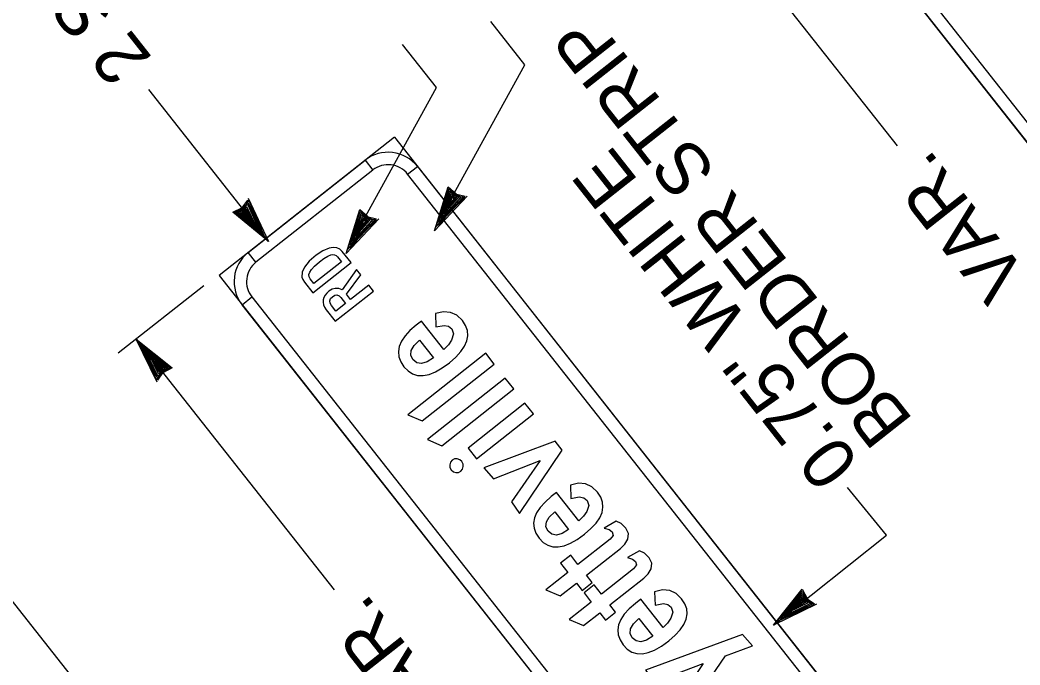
# Model space of a CAD drawing. Extents: x 672126 to 673696, y 1673540 to 1674900.
# Drawn here: x 672217.5 to 672298.2, y 1674630.5 to 1674682.5 of the extents above; entities that cross this region are included whole.
import ezdxf

# ---------------------------------------------------------------- set-up
doc = ezdxf.new("R2010")
doc.units = 0
for name, color, linetype in [('61', 7, 'Continuous'), ('C-ANNO-SYMB', 7, 'Continuous'), ('Level 1', 7, 'Continuous')]:
    doc.layers.add(name, color=color, linetype=linetype)

msp = doc.modelspace()

# ---------------------------------------------------------------- linework, layer by layer
at = {"layer": '61'}
msp.add_lwpolyline([(672259.689, 1674581.406), (672186.159, 1674674.677), (672163.206, 1674656.582), (672236.736, 1674563.312)], close=True, dxfattribs=at)
at = {"layer": 'C-ANNO-SYMB'}
for p, q in [((672275.262, 1674702.456), (672319.838, 1674645.914)), ((672247.706, 1674673.092), (672233.571, 1674661.948)), ((672247.706, 1674673.092), (672288.567, 1674621.261)), ((672245.35, 1674671.234), (672245.969, 1674670.449)), ((672248.778, 1674670.117), (672249.564, 1674670.736)), ((672236.546, 1674663.02), (672235.927, 1674663.805)), ((672233.571, 1674661.948), (672274.431, 1674610.117)), ((672235.428, 1674659.592), (672236.213, 1674660.211))]:
    msp.add_line(p, q, dxfattribs=at)
for points in [[(672277.905, 1674700.719), (672318.766, 1674648.889), (672317.98, 1674648.27), (672277.12, 1674700.1), (672277.905, 1674700.719), (672277.905, 1674700.719)], [(672245.969, 1674670.449), (672236.546, 1674663.02), (672235.927, 1674663.805), (672245.35, 1674671.234), (672245.969, 1674670.449), (672245.969, 1674670.449)], [(672285.924, 1674622.998), (672248.778, 1674670.117), (672249.564, 1674670.736), (672286.71, 1674623.617), (672285.924, 1674622.998), (672285.924, 1674622.998)], [(672236.213, 1674660.211), (672273.359, 1674613.092), (672272.574, 1674612.473), (672235.428, 1674659.592), (672236.213, 1674660.211), (672236.213, 1674660.211)], [(672255.756, 1674654.804), (672255.071, 1674655.674), (672248.788, 1674650.721), (672249.95, 1674650.227)], [(672257.341, 1674652.794), (672256.656, 1674653.664), (672250.373, 1674648.711), (672251.535, 1674648.217)], [(672258.926, 1674650.784), (672258.24, 1674651.653), (672253.65, 1674648.034), (672254.335, 1674647.165)], [(672257.802, 1674642.767), (672261.237, 1674647.852), (672260.664, 1674648.579), (672254.912, 1674646.433), (672255.696, 1674645.551), (672259.462, 1674647.025), (672257.166, 1674643.686)], [(672253.076, 1674646.172), (672253.212, 1674646.33), (672253.267, 1674646.532), (672253.246, 1674646.746), (672253.141, 1674646.939), (672252.975, 1674647.092), (672252.775, 1674647.168), (672252.569, 1674647.161), (672252.375, 1674647.061), (672252.233, 1674646.896), (672252.169, 1674646.69), (672252.19, 1674646.473), (672252.295, 1674646.273), (672252.465, 1674646.124), (672252.673, 1674646.058), (672252.888, 1674646.072)], [(672264.626, 1674641.585), (672265.042, 1674641.455), (672265.278, 1674641.283), (672265.345, 1674640.996), (672265.1, 1674640.689), (672262.516, 1674638.652), (672261.937, 1674639.386), (672261.117, 1674638.74), (672261.696, 1674638.006), (672259.918, 1674636.604), (672261.08, 1674636.109), (672262.382, 1674637.136), (672262.842, 1674636.553), (672263.662, 1674637.199), (672263.202, 1674637.782), (672265.933, 1674639.935), (672266.301, 1674640.292), (672266.526, 1674640.675), (672266.582, 1674641.142), (672266.385, 1674641.57), (672266.004, 1674641.941), (672265.584, 1674642.13)], [(672266.508, 1674639.198), (672266.924, 1674639.067), (672267.16, 1674638.895), (672267.227, 1674638.609), (672266.982, 1674638.302), (672264.398, 1674636.265), (672263.819, 1674636.999), (672263, 1674636.353), (672263.578, 1674635.619), (672261.8, 1674634.217), (672262.962, 1674633.722), (672264.264, 1674634.748), (672264.724, 1674634.165), (672265.544, 1674634.812), (672265.084, 1674635.394), (672267.815, 1674637.547), (672268.183, 1674637.904), (672268.408, 1674638.287), (672268.464, 1674638.754), (672268.267, 1674639.183), (672267.886, 1674639.553), (672267.466, 1674639.743)], [(672276.595, 1674632.098), (672275.794, 1674632.989), (672267.961, 1674630.13), (672268.701, 1674629.191), (672272.617, 1674630.656), (672270.294, 1674627.171), (672270.999, 1674626.277), (672274.405, 1674631.287)]]:
    msp.add_lwpolyline(points, close=True, dxfattribs=at)
for points in [[(672244.214, 1674662.985), (672243.506, 1674663.882), (672243.306, 1674664.07), (672243.061, 1674664.177), (672242.775, 1674664.203), (672242.443, 1674664.148), (672241.926, 1674663.936), (672241.4, 1674663.587), (672240.842, 1674663.092), (672240.463, 1674662.629), (672240.265, 1674662.201), (672240.246, 1674661.807), (672240.322, 1674661.618), (672240.47, 1674661.398), (672241.133, 1674660.556), (672244.214, 1674662.985)], [(672243.436, 1674663.057), (672241.209, 1674661.301), (672240.924, 1674661.662), (672240.834, 1674661.832), (672240.819, 1674662.018), (672240.881, 1674662.218), (672241.017, 1674662.433), (672241.269, 1674662.697), (672241.673, 1674663.038), (672242.021, 1674663.313), (672242.337, 1674663.508), (672242.578, 1674663.611), (672242.743, 1674663.636), (672242.89, 1674663.615), (672243.022, 1674663.549), (672243.135, 1674663.439), (672243.436, 1674663.057)], [(672246.022, 1674660.692), (672245.641, 1674661.175), (672244.174, 1674660.018), (672243.85, 1674660.43), (672244.999, 1674661.989), (672244.65, 1674662.431), (672243.485, 1674660.786), (672243.226, 1674660.892), (672242.942, 1674660.904), (672242.68, 1674660.831), (672242.432, 1674660.682), (672242.258, 1674660.523), (672242.123, 1674660.353), (672242.029, 1674660.173), (672241.975, 1674659.984), (672241.964, 1674659.781), (672242.001, 1674659.58), (672242.084, 1674659.381), (672242.214, 1674659.185), (672242.941, 1674658.263), (672246.022, 1674660.692)], [(672243.768, 1674659.699), (672242.983, 1674659.08), (672242.627, 1674659.532), (672242.529, 1674659.711), (672242.509, 1674659.901), (672242.57, 1674660.081), (672242.711, 1674660.236), (672242.902, 1674660.347), (672243.079, 1674660.372), (672243.246, 1674660.312), (672243.4, 1674660.166), (672243.768, 1674659.699)], [(672251.693, 1674655.984), (672249.889, 1674658.272), (672249.464, 1674657.937), (672248.964, 1674657.5), (672248.567, 1674657.067), (672248.282, 1674656.641), (672248.102, 1674656.221), (672248.035, 1674655.804), (672248.074, 1674655.394), (672248.225, 1674654.989), (672248.48, 1674654.592), (672248.813, 1674654.252), (672249.18, 1674654.018), (672249.585, 1674653.894), (672250.023, 1674653.881), (672250.503, 1674653.975), (672251.015, 1674654.18), (672251.563, 1674654.493), (672252.15, 1674654.915), (672252.668, 1674655.364), (672253.076, 1674655.805), (672253.374, 1674656.239), (672253.558, 1674656.665), (672253.636, 1674657.084), (672253.598, 1674657.499), (672253.451, 1674657.906), (672253.192, 1674658.305), (672252.747, 1674658.734), (672252.236, 1674658.972), (672251.66, 1674659.02), (672251.014, 1674658.875), (672251.051, 1674657.795), (672251.725, 1674657.923), (672252.081, 1674657.851), (672252.347, 1674657.639), (672252.484, 1674657.236), (672252.327, 1674656.736), (672252.061, 1674656.351), (672251.693, 1674655.984)], [(672250.866, 1674655.293), (672250.349, 1674654.971), (672249.899, 1674654.842), (672249.518, 1674654.906), (672249.205, 1674655.162), (672249.037, 1674655.516), (672249.068, 1674655.896), (672249.304, 1674656.296), (672249.74, 1674656.721), (672250.866, 1674655.293)], [(672262.589, 1674642.163), (672260.785, 1674644.45), (672260.36, 1674644.115), (672259.86, 1674643.679), (672259.463, 1674643.246), (672259.178, 1674642.82), (672258.998, 1674642.4), (672258.932, 1674641.983), (672258.971, 1674641.572), (672259.122, 1674641.168), (672259.376, 1674640.771), (672259.709, 1674640.431), (672260.076, 1674640.197), (672260.481, 1674640.072), (672260.919, 1674640.059), (672261.399, 1674640.154), (672261.911, 1674640.358), (672262.46, 1674640.672), (672263.046, 1674641.094), (672263.564, 1674641.542), (672263.972, 1674641.983), (672264.27, 1674642.418), (672264.454, 1674642.844), (672264.532, 1674643.263), (672264.495, 1674643.677), (672264.348, 1674644.085), (672264.088, 1674644.483), (672263.643, 1674644.912), (672263.132, 1674645.15), (672262.556, 1674645.198), (672261.91, 1674645.053), (672261.947, 1674643.973), (672262.621, 1674644.102), (672262.977, 1674644.029), (672263.243, 1674643.817), (672263.38, 1674643.414), (672263.224, 1674642.914), (672262.957, 1674642.53), (672262.589, 1674642.163)], [(672261.762, 1674641.471), (672261.245, 1674641.149), (672260.795, 1674641.021), (672260.414, 1674641.085), (672260.102, 1674641.341), (672259.934, 1674641.694), (672259.965, 1674642.075), (672260.2, 1674642.474), (672260.636, 1674642.9), (672261.762, 1674641.471)], [(672269.374, 1674633.555), (672267.571, 1674635.843), (672267.146, 1674635.508), (672266.646, 1674635.072), (672266.248, 1674634.639), (672265.963, 1674634.213), (672265.784, 1674633.793), (672265.717, 1674633.376), (672265.756, 1674632.965), (672265.907, 1674632.561), (672266.161, 1674632.164), (672266.494, 1674631.823), (672266.861, 1674631.589), (672267.267, 1674631.465), (672267.705, 1674631.452), (672268.185, 1674631.547), (672268.696, 1674631.751), (672269.245, 1674632.065), (672269.831, 1674632.487), (672270.349, 1674632.935), (672270.758, 1674633.376), (672271.056, 1674633.811), (672271.24, 1674634.237), (672271.317, 1674634.656), (672271.28, 1674635.07), (672271.133, 1674635.478), (672270.873, 1674635.876), (672270.428, 1674636.305), (672269.918, 1674636.543), (672269.341, 1674636.591), (672268.696, 1674636.446), (672268.733, 1674635.366), (672269.406, 1674635.495), (672269.763, 1674635.422), (672270.028, 1674635.21), (672270.166, 1674634.807), (672270.009, 1674634.307), (672269.742, 1674633.923), (672269.374, 1674633.555)], [(672268.548, 1674632.864), (672268.03, 1674632.542), (672267.581, 1674632.414), (672267.2, 1674632.478), (672266.887, 1674632.734), (672266.719, 1674633.087), (672266.75, 1674633.468), (672266.986, 1674633.867), (672267.421, 1674634.293), (672268.548, 1674632.864)]]:
    msp.add_lwpolyline(points, dxfattribs=at)
for centre, radius, start, end in [((672247.208, 1674668.879), 3, 38.2506, 128.25081), ((672247.208, 1674668.879), 2, 38.2506, 128.25081), ((672237.784, 1674661.449), 3, 128.25054, 218.25075), ((672237.784, 1674661.449), 2, 128.25054, 218.25075)]:
    msp.add_arc(centre, radius, start, end, dxfattribs=at)
at = {"layer": 'Level 1'}
for p, q in [((672288.283, 1674672.401), (672272.326, 1674692.642)), ((672237.554, 1674664.676), (672227.895, 1674676.927)), ((672250.934, 1674665.541), (672252.051, 1674669.091)), ((672252.051, 1674669.091), (672252.69, 1674668.524)), ((672253.589, 1674668.34), (672250.934, 1674665.541)), ((672251.052, 1674665.839), (672252.087, 1674668.945)), ((672253.388, 1674668.26), (672251.197, 1674666.028)), ((672251.28, 1674666.223), (672252.145, 1674668.787)), ((672251.448, 1674666.395), (672252.281, 1674668.555)), ((672253.081, 1674668.259), (672251.448, 1674666.395)), ((672251.471, 1674666.536), (672252.194, 1674668.665)), ((672253.081, 1674668.259), (672251.471, 1674666.536)), ((672251.753, 1674667.009), (672252.281, 1674668.401)), ((672252.893, 1674668.249), (672251.753, 1674667.009)), ((672252.017, 1674667.4), (672252.294, 1674668.27)), ((672252.087, 1674668.945), (672252.609, 1674668.541)), ((672252.331, 1674668.434), (672252.132, 1674667.544)), ((672252.145, 1674668.787), (672252.368, 1674668.595)), ((672252.194, 1674668.665), (672253.081, 1674668.259)), ((672252.281, 1674668.555), (672252.893, 1674668.249)), ((672252.281, 1674668.401), (672252.727, 1674668.228)), ((672252.294, 1674668.27), (672252.609, 1674668.235)), ((672252.779, 1674668.317), (672252.331, 1674668.434)), ((672252.368, 1674668.595), (672253.081, 1674668.259)), ((672252.45, 1674668.178), (672252.779, 1674668.317)), ((672252.609, 1674668.541), (672253.405, 1674668.342)), ((672252.69, 1674668.524), (672253.027, 1674668.322)), ((672253.027, 1674668.322), (672253.388, 1674668.26)), ((672253.178, 1674668.322), (672253.22, 1674668.236)), ((672235.141, 1674667.028), (672235.854, 1674667.694)), ((672235.273, 1674667.162), (672235.854, 1674667.694)), ((672235.276, 1674667.067), (672235.792, 1674667.516)), ((672235.414, 1674667.365), (672235.901, 1674668.025)), ((672235.461, 1674667.433), (672235.776, 1674667.668)), ((672235.776, 1674667.668), (672235.97, 1674667.979)), ((672235.792, 1674667.516), (672236.506, 1674665.991)), ((672235.901, 1674668.025), (672235.833, 1674667.807)), ((672235.833, 1674667.807), (672235.929, 1674667.814)), ((672235.854, 1674667.694), (672236.837, 1674665.55)), ((672235.854, 1674667.694), (672236.959, 1674665.476)), ((672235.922, 1674668.172), (672237.554, 1674664.676)), ((672235.929, 1674667.814), (672237.291, 1674664.941)), ((672235.97, 1674667.979), (672237.203, 1674665.104)), ((672253.22, 1674668.236), (672251.08, 1674665.884)), ((672252.132, 1674667.544), (672251.932, 1674667.359)), ((672252.727, 1674668.228), (672252.017, 1674667.4)), ((672252.609, 1674668.235), (672252.224, 1674667.796)), ((672252.224, 1674667.796), (672252.35, 1674668.209)), ((672252.35, 1674668.209), (672252.45, 1674668.178)), ((672234.694, 1674667.057), (672235.461, 1674667.433)), ((672237.554, 1674664.676), (672234.694, 1674667.057)), ((672234.842, 1674667.035), (672235.414, 1674667.365)), ((672237.322, 1674664.898), (672234.842, 1674667.035)), ((672235.01, 1674667.029), (672235.273, 1674667.162)), ((672237.054, 1674665.255), (672235.01, 1674667.029)), ((672236.837, 1674665.55), (672235.141, 1674667.028)), ((672236.959, 1674665.476), (672235.276, 1674667.067)), ((672235.686, 1674667.437), (672235.408, 1674667.067)), ((672235.408, 1674667.067), (672236.155, 1674666.545)), ((672235.419, 1674667.008), (672235.749, 1674667.355)), ((672236.506, 1674665.991), (672235.419, 1674667.008)), ((672235.545, 1674666.97), (672235.697, 1674667.248)), ((672236.245, 1674666.384), (672235.545, 1674666.97)), ((672235.623, 1674666.999), (672235.69, 1674667.079)), ((672235.957, 1674666.726), (672235.623, 1674666.999)), ((672235.69, 1674667.079), (672235.686, 1674667.437)), ((672235.697, 1674667.248), (672235.957, 1674666.726)), ((672235.749, 1674667.355), (672236.245, 1674666.384)), ((672243.809, 1674663.711), (672244.926, 1674667.261)), ((672243.928, 1674664.01), (672244.963, 1674667.116)), ((672244.156, 1674664.393), (672245.021, 1674666.958)), ((672244.324, 1674664.565), (672245.156, 1674666.726)), ((672244.346, 1674664.706), (672245.07, 1674666.836)), ((672244.926, 1674667.261), (672245.566, 1674666.694)), ((672244.963, 1674667.116), (672245.484, 1674666.711)), ((672245.021, 1674666.958), (672245.243, 1674666.765)), ((672245.07, 1674666.836), (672245.956, 1674666.43)), ((672245.156, 1674666.726), (672245.768, 1674666.42)), ((672245.243, 1674666.765), (672245.956, 1674666.43)), ((672245.484, 1674666.711), (672246.28, 1674666.512)), ((672245.566, 1674666.694), (672245.903, 1674666.492)), ((672251.263, 1674665.986), (672251.855, 1674666.671)), ((672251.855, 1674666.671), (672251.28, 1674666.223)), ((672251.932, 1674667.359), (672251.721, 1674666.905)), ((672251.721, 1674666.905), (672252.052, 1674667.255)), ((672236.155, 1674666.545), (672236.25, 1674666.29)), ((672246.464, 1674666.51), (672243.809, 1674663.711)), ((672246.095, 1674666.406), (672243.955, 1674664.054)), ((672246.264, 1674666.43), (672244.072, 1674664.198)), ((672245.956, 1674666.43), (672244.324, 1674664.565)), ((672245.956, 1674666.43), (672244.346, 1674664.706)), ((672244.629, 1674665.179), (672245.157, 1674666.571)), ((672245.768, 1674666.42), (672244.629, 1674665.179)), ((672244.893, 1674665.57), (672245.169, 1674666.44)), ((672245.602, 1674666.398), (672244.893, 1674665.57)), ((672245.207, 1674666.604), (672245.008, 1674665.715)), ((672245.484, 1674666.405), (672245.1, 1674665.966)), ((672245.1, 1674665.966), (672245.225, 1674666.379)), ((672245.157, 1674666.571), (672245.602, 1674666.398)), ((672245.169, 1674666.44), (672245.484, 1674666.405)), ((672245.655, 1674666.487), (672245.207, 1674666.604)), ((672245.225, 1674666.379), (672245.325, 1674666.348)), ((672245.325, 1674666.348), (672245.655, 1674666.487)), ((672245.903, 1674666.492), (672246.264, 1674666.43)), ((672246.053, 1674666.492), (672246.095, 1674666.406)), ((672244.808, 1674665.53), (672244.596, 1674665.075)), ((672244.596, 1674665.075), (672244.927, 1674665.426)), ((672245.008, 1674665.715), (672244.808, 1674665.53)), ((672244.138, 1674664.157), (672244.731, 1674664.841)), ((672244.731, 1674664.841), (672244.156, 1674664.393)), ((672232.338, 1674661.117), (672225.434, 1674655.675)), ((672228.582, 1674653.351), (672226.878, 1674656.813)), ((672226.878, 1674656.813), (672229.787, 1674654.492)), ((672242.869, 1674636.599), (672226.912, 1674656.84)), ((672227.238, 1674656.392), (672227.114, 1674656.595)), ((672227.114, 1674656.595), (672229.638, 1674654.51)), ((672228.568, 1674653.709), (672227.146, 1674656.553)), ((672227.146, 1674656.553), (672227.175, 1674656.346)), ((672227.175, 1674656.346), (672227.6, 1674655.546)), ((672228.529, 1674653.544), (672227.238, 1674656.392)), ((672227.6, 1674655.546), (672227.39, 1674656.244)), ((672227.39, 1674656.244), (672229.47, 1674654.513)), ((672228.64, 1674653.83), (672227.489, 1674656.025)), ((672227.489, 1674656.025), (672229.205, 1674654.47)), ((672228.64, 1674653.83), (672227.613, 1674655.953)), ((672227.613, 1674655.953), (672229.338, 1674654.511)), ((672228.214, 1674655.226), (672227.867, 1674655.587)), ((672227.867, 1674655.587), (672228.074, 1674655.152)), ((672228.699, 1674654.009), (672227.952, 1674655.52)), ((672227.952, 1674655.52), (672229.06, 1674654.525)), ((672228.315, 1674654.973), (672228.214, 1674655.226)), ((672228.738, 1674654.172), (672228.221, 1674655.132)), ((672228.221, 1674655.132), (672228.933, 1674654.561)), ((672229.073, 1674654.467), (672228.315, 1674654.973)), ((672228.787, 1674654.279), (672228.517, 1674654.797)), ((672228.517, 1674654.797), (672228.856, 1674654.531)), ((672228.933, 1674654.561), (672228.787, 1674654.279)), ((672228.717, 1674653.858), (672228.529, 1674653.544)), ((672229.073, 1674654.169), (672228.6, 1674653.498)), ((672229.338, 1674654.511), (672228.64, 1674653.83)), ((672229.21, 1674654.375), (672228.64, 1674653.83)), ((672229.205, 1674654.47), (672228.699, 1674654.009)), ((672229.027, 1674654.099), (672228.717, 1674653.858)), ((672229.06, 1674654.525), (672228.738, 1674654.172)), ((672228.856, 1674654.531), (672228.791, 1674654.448)), ((672228.791, 1674654.448), (672228.802, 1674654.091)), ((672228.802, 1674654.091), (672229.073, 1674654.467)), ((672229.787, 1674654.492), (672229.027, 1674654.099)), ((672229.638, 1674654.51), (672229.073, 1674654.169)), ((672229.47, 1674654.513), (672229.21, 1674654.375)), ((672228.663, 1674653.718), (672228.568, 1674653.709)), ((672278.286, 1674633.743), (672280.606, 1674636.653)), ((672278.504, 1674633.979), (672280.588, 1674636.505)), ((672278.855, 1674634.255), (672280.585, 1674636.336)), ((672279.074, 1674634.355), (672280.628, 1674636.071)), ((672279.145, 1674634.479), (672280.587, 1674636.205)), ((672280.585, 1674636.336), (672280.723, 1674636.076)), ((672280.587, 1674636.205), (672281.268, 1674635.507)), ((672280.588, 1674636.505), (672280.929, 1674635.94)), ((672280.606, 1674636.653), (672280.998, 1674635.894)), ((672280.628, 1674636.071), (672281.089, 1674635.565)), ((672280.723, 1674636.076), (672281.268, 1674635.507)), ((672281.747, 1674635.449), (672278.286, 1674633.743)), ((672281.389, 1674635.435), (672278.546, 1674634.011)), ((672281.555, 1674635.397), (672278.707, 1674634.103)), ((672281.268, 1674635.507), (672279.074, 1674634.355)), ((672281.268, 1674635.507), (672279.145, 1674634.479)), ((672279.579, 1674634.818), (672280.573, 1674635.927)), ((672281.089, 1674635.565), (672279.579, 1674634.818)), ((672279.966, 1674635.088), (672280.537, 1674635.8)), ((672280.926, 1674635.605), (672279.966, 1674635.088)), ((672280.631, 1674635.94), (672280.126, 1674635.181)), ((672280.302, 1674635.383), (672280.567, 1674635.723)), ((672280.819, 1674635.654), (672280.302, 1674635.383)), ((672280.537, 1674635.8), (672280.819, 1674635.654)), ((672280.567, 1674635.723), (672280.65, 1674635.658)), ((672280.573, 1674635.927), (672280.926, 1674635.605)), ((672281.007, 1674635.669), (672280.631, 1674635.94)), ((672280.65, 1674635.658), (672281.007, 1674635.669)), ((672280.929, 1674635.94), (672281.6, 1674635.467)), ((672280.998, 1674635.894), (672281.24, 1674635.584)), ((672281.24, 1674635.584), (672281.555, 1674635.397)), ((672281.6, 1674635.467), (672281.381, 1674635.53)), ((672281.381, 1674635.53), (672281.389, 1674635.435)), ((672280.126, 1674635.181), (672279.872, 1674635.081))]:
    msp.add_line(p, q, dxfattribs=at)
for points in [[(672252.072, 1674667.748), (672258.234, 1674678.925), (672255.488, 1674682.408)], [(672244.947, 1674665.919), (672251.109, 1674677.095), (672248.364, 1674680.578)], [(672278.286, 1674633.743), (672287.399, 1674641.004), (672284.261, 1674644.86)]]:
    msp.add_lwpolyline(points, dxfattribs=at)

# ---------------------------------------------------------------- texts
for s, p in [('2 SIGNS REQUIRED', (672228.252, 1674679.465)), ('BORDER STRIP', (672289.626, 1674650.257)), ('0.75" WHITE ', (672285.332, 1674646.872)), ('VAR.', (672298.867, 1674661.956)), ('VAR.', (672253.453, 1674626.153))]:
    msp.add_text(s, height=4.2, rotation=128.25054, dxfattribs=at).set_placement(p)

doc.saveas('drawing.dxf')
